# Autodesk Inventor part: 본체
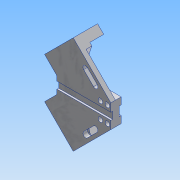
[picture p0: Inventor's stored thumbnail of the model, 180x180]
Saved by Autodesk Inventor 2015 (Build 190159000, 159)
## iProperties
Created: 2019-04
Part Number: 본체
Material: 알루미늄 6061
Document SubType Name: Modeling
Designer: user
Density: 2.7 g/cm^3
Appearance: 알루미늄 - 평지
Mass: 648.928 g
Surface Area: 455.697 cm^2
Volume: 240.344 cm^3
Author: user
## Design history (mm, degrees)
sketch "스케치1"
  geometry: L1 (-46.5, 20)-(46.5, 20); L2 (46.5, 20)-(46.5, -20); L3 (46.5, -20)-(-46.5, -20); L4 (-46.5, -20)-(-46.5, 20); L5 (-46.5, 20)-(46.5, -20); L6 (46.5, 20)-(-46.5, -20); 1 further point
  constraints: 12 end point, 2 midpoint, 2 parallel, 1 horizontal, 1 perpendicular
  dimensions: "d1" = 93 distance of L2.end L3.end; "d2" = 40 distance of L1.end L2.end
extrude "돌출1" new body sketch "스케치1" distance "d3" = 18; taper "d4" = 0 deg
sketch "스케치4"
  geometry: L1 (-46.5, 20)-(-46.5, -20) reference; L2 (-46.5, -8)-(46.5, -8); L3 (46.5, -8)-(46.5, 8); L4 (46.5, 8)-(-46.5, 8); L5 (-46.5, 8)-(-46.5, -8); L6 (46.5, -20)-(46.5, 20) reference; 4 further points
  constraints: 8 end point, 2 midpoint, 2 parallel, 1 horizontal, 1 perpendicular, 1 point on line
  dimensions: "d21" = 16 distance of L2.end L3.end
extrude "돌출4" cut sketch "스케치4" distance "d22" = 3.5; taper "d23" = 0 deg
sketch "스케치5"
  geometry: L1 (-46.5, 20)-(-46.5, -20) reference; L2 (-46.5, -6)-(46.5, -6); L3 (46.5, -6)-(46.5, 6); L4 (46.5, 6)-(-46.5, 6); L5 (-46.5, 6)-(-46.5, -6); L6 (46.5, -20)-(46.5, 20) reference; 6 further points
  constraints: 8 end point, 3 midpoint, 2 horizontal alignment, 2 parallel, 1 horizontal, 1 perpendicular, 1 point on line
  dimensions: "d24" = 12 distance of L2.end L3.end
extrude "돌출5" cut sketch "스케치5" distance "d25" = 3; taper "d26" = 0 deg
sketch "스케치8"
  geometry: L1 (46.5, -20)-(46.5, -6) reference; 3 further points
  dimensions: "d39" = 6 distance from line of L1 point (40.5, -14); "d40" = 14 vertical distance of point (0, 0) point (40.5, -14); "d41" = 12 distance of point (40.5, -14) point (28.5, -14); "d42" = 14 vertical distance of point (0, 0) point (28.5, -14)
hole "구멍1" sketch "스케치8" at (40.5, -14), (28.5, -14) diameter "d43" = 4.5; stored, may be unused: countersink angle "d47" = 90 deg, drill point angle "d49" = 118 deg; dims "d44" = 6, "d45" = 8, "d46" = 10, "d48" = 8
sketch "스케치10"
  geometry: L1 (-46.5, -8)-(-46.5, 8) reference; L2 (-46.5, 0)-(-66.5, 0); L3 (-46.5, -20)-(18.353, -84.853); L4 (18.353, -84.853)-(67.85, -35.355); L5 (67.85, -35.355)-(46.5, -14.005); L6 (46.5, -20)-(46.5, -8) reference; L7 (-46.5, -20)-(46.5, -20) reference; L8 (46.5, -14.005)-(46.5, -20); L9 (46.5, -20)-(-46.5, -20); L10 (46.5, -14.005)-(46.5, -20); L11 (46.5, -20)-(-46.5, -20); 1 further point
  constraints: 16 end point, 2 point on line, 2 vertical, 1 collinear, 1 horizontal, 1 midpoint, 1 perpendicular
  dimensions: "d62" = 20 distance of L2.start L2.end; "d63" = 120 distance of L2.end L3.end; "d64" = 45 deg angle of L2 L3; "d65" = 70 distance of L3.end L4.end; "d66" = 90 deg angle of L3 L4; "d67" = 91.71573 distance of L3.start L3.end; "d68" = 30.19387 distance of L4.end L5.end
extrude "돌출8" join sketch "스케치10" distance "d69" = 18; taper "d70" = 0 deg
sketch "스케치11"
  geometry: L1 (46.5, 20)-(-18.353, 84.853) reference; L2 (-18.353, 84.853)-(-67.85, 35.355) reference; L3 (-67.85, 35.355)-(-46.5, 14.005) reference; L4 (-57.244, 24.749)-(-7.746, 74.246); L5 (-57.244, 24.749)-(-67.85, 35.355); L6 (-67.85, 35.355)-(-18.353, 84.853); L7 (-18.353, 84.853)-(-7.746, 74.246); 1 further point
  constraints: 8 end point, 2 perpendicular, 2 point on line, 1 collinear
  dimensions: "d71" = 15 distance between parallel lines of L2 L4
extrude "돌출9" join sketch "스케치11" distance "d72" = 24; taper "d73" = 0 deg
sketch "스케치12"
  geometry: L1 (46.5, -20)-(-7.746, -74.246) reference; L2 (-4.211, -70.711)-(-11.282, -49.497); L3 (-11.282, -49.497)-(18.216, -20); L4 (18.216, -20)-(46.5, -20); L5 (-18.353, -84.853)-(-67.85, -35.355) reference; L6 (-11.282, -49.497)-(2.86, -63.64); L7 (-4.211, -70.711)-(46.5, -20); 1 further point
  constraints: 10 end point, 2 point on line, 1 horizontal, 1 parallel, 1 perpendicular
  dimensions: "d74" = 20 distance from line of L5 L2.start; "d75" = 30 distance of L5.start L6.end; "d76" = 20 distance of L6.end L2.end
extrude "돌출10" cut sketch "스케치12" distance "d77" = 10; taper "d78" = 0 deg
sketch "스케치13"
  geometry: L1 (46.5, -20)-(-4.211, -70.711) reference; L2 (2.86, -49.497)-(19.831, -32.527); L3 (-7.746, -74.246)-(-18.353, -84.853) reference; L4 (2.86, -49.497)-(9.931, -56.569); L5 (2.86, -49.497)-(19.831, -32.527); L6 (6.042, -52.679)-(23.013, -35.709); L7 (16.649, -29.345)-(-0.322, -46.315); A1 r 4.5 centre (2.86, -49.497) between (-0.322, -46.315) and (6.042, -52.679); A2 r 4.5 centre (19.831, -32.527) between (23.013, -35.709) and (16.649, -29.345); 2 further points
  constraints: 12 end point, 4 point on circle, 4 tangent, 2 centre point, 2 parallel, 1 collinear, 1 midpoint, 1 perpendicular, 1 point on line
  dimensions: "d79" = 10 distance from line of L3 L2.start; "d80" = 40 distance of L3.end L4.end; "d82" = 24 distance of L2.start L2.end; "d83" = 9 diameter of A2
extrude "돌출11" cut sketch "스케치13" distance "d84" = 10; taper "d85" = 0 deg
fillet "모깎기3" dims "d86" = 5
fillet "모깎기4" dims "d87" = 5
sketch "스케치14"
  geometry: L1 (0, 0)-(0, 70) reference; L2 (0, 70)-(15, 70) reference; 2 further points
  constraints: 1 other
  dimensions: "d88" = 7.5 distance from line of L1 point (7.5, 35); "d89" = 35 distance from line of L2 point (7.5, 35)
feature "엠보싱2" sketch "스케치14" dims "d1" = 93, "d2" = 40, "d90" = 0.5, "d91" = 0
node "솔리드1"
mirror "대칭5"
mirror "대칭6"
mirror "대칭7"
mirror "대칭8"
